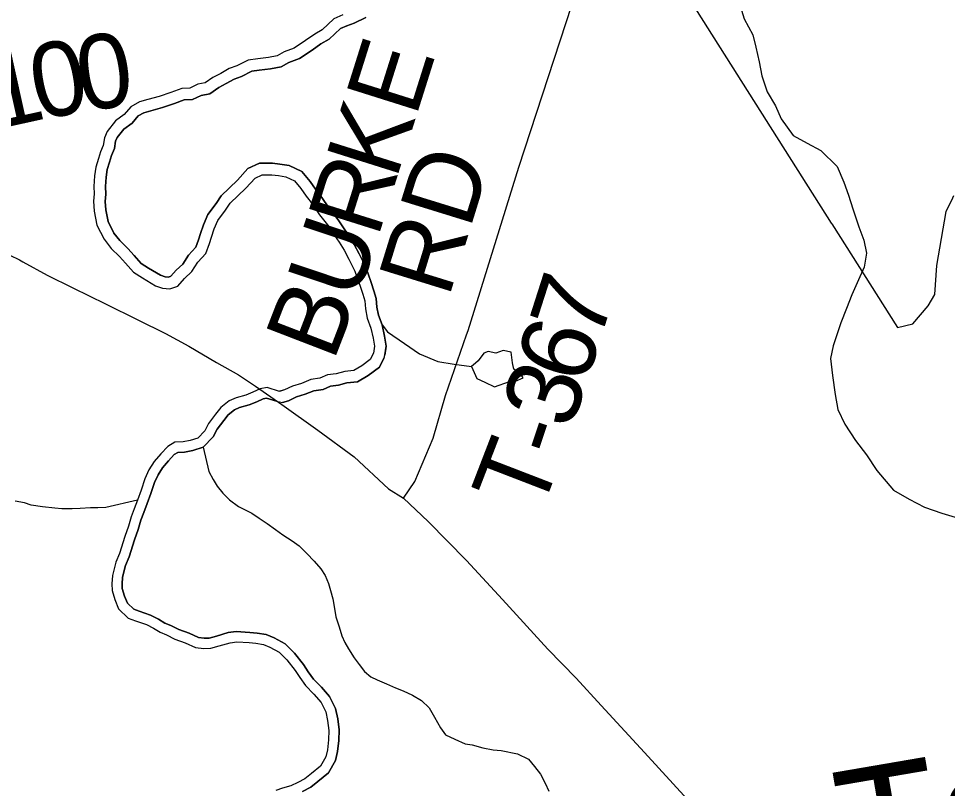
# Model space of a CAD drawing. Extents: x 1310247 to 1664935, y 235267 to 584339.
# Drawn here: x 1510976 to 1514722, y 357083 to 360189 of the extents above; entities that cross this region are included whole.
import ezdxf

# ---------------------------------------------------------------- set-up
doc = ezdxf.new("R2010")
doc.units = 0
for name, color, linetype in [('GM_X_Minor_Lake', 7, 'Continuous'), ('GM_X_Minor_River', 7, 'Continuous'), ('GM_X_Minor_River_Text', 7, 'Continuous'), ('GM_X_State_Route', 7, 'Continuous'), ('GM_X_Township_Road', 7, 'Continuous'), ('GM_X_Township_Road_Text', 7, 'Continuous'), ('GM_X_Township_ROW', 7, 'Continuous')]:
    doc.layers.add(name, color=color, linetype=linetype)

msp = doc.modelspace()

# ---------------------------------------------------------------- linework, layer by layer
at = {"layer": 'GM_X_Minor_Lake'}
for points in [[(1512802.7, 358784.8), (1512823.9, 358736.2), (1512855.8, 358721.6), (1512895.6, 358702.9), (1512956.1, 358724), (1512980.2, 358725.6), (1513010.5, 358739.1), (1512996.8, 358759.4), (1512973, 358773.9), (1512967.4, 358800.1), (1512962.1, 358842.3), (1512930.1, 358848.9), (1512899.9, 358839.4), (1512869.9, 358845.9)], [(1512869.9, 358845.9), (1512851.7, 358838.2), (1512829.1, 358808.4), (1512818.9, 358798.5), (1512802.7, 358784.8)]]:
    msp.add_lwpolyline(points, dxfattribs=at)
at = {"layer": 'GM_X_Minor_River'}
msp.add_line((1512015.5, 358644.9), (1512040.2, 358639.7), dxfattribs=at)
for points in [[(1513885.8, 360240.7), (1513901.4, 360188.1), (1513936.4, 360123.3), (1513949.6, 360072.9), (1513962.7, 360014.4), (1513973.8, 359958), (1513994.8, 359893.4), (1514027.9, 359836.6), (1514051.1, 359784), (1514100.1, 359716.9), (1514155.8, 359685.9), (1514211.5, 359656.8), (1514276.6, 359591.5), (1514303.6, 359528.8), (1514322.8, 359476.2), (1514340, 359421.7), (1514364.8, 359349), (1514384, 359294.5), (1514395.2, 359242.1), (1514386.2, 359186), (1514363.3, 359134.2), (1514336.2, 359074.4), (1514315.2, 359018.5), (1514292.2, 358960.6), (1514260.5, 358868.8), (1514249.6, 358816.8), (1514258.5, 358748.3), (1514269.3, 358671.9), (1514280.3, 358611.4), (1514307.4, 358552.7), (1514350.4, 358485.8), (1514395.6, 358428.8), (1514436.7, 358365.8), (1514503.6, 358286.4), (1514567.2, 358249.2), (1514628.8, 358218), (1514698.6, 358192.8), (1514766.5, 358173.6)], [(1512283.5, 360203.5), (1512247.2, 360188.3), (1512200.2, 360143.2), (1512169.9, 360125.8), (1512133.3, 360100.5), (1512086.7, 360069.5), (1512046.4, 360054.3), (1512018.1, 360038.9), (1511984, 360031.6), (1511940, 360026.6), (1511901.9, 360021.4), (1511855.4, 359998.4), (1511825.2, 359987), (1511790.8, 359967.7), (1511758.5, 359950.4), (1511728.1, 359929), (1511698, 359923.6), (1511665.7, 359908.3), (1511633.7, 359907), (1511589.4, 359889.9), (1511543.1, 359874.9), (1511496.9, 359861.9), (1511462.7, 359852.6), (1511428.3, 359833.3), (1511401.6, 359801.8), (1511367.1, 359776.5), (1511332.2, 359733.2), (1511321.6, 359707.3), (1511317, 359677.3), (1511306.4, 359651.5), (1511297.8, 359623.6), (1511287, 359589.8), (1511282.2, 359553.8), (1511279.3, 359511.7), (1511280.6, 359481.6), (1511277.9, 359451.5), (1511281, 359411.4), (1511291.8, 359355), (1511320.4, 359298.2), (1511349.6, 359261.4), (1511382.8, 359228.6), (1511406.2, 359202), (1511439.3, 359165.2), (1511474.7, 359142.3), (1511528, 359111), (1511555.7, 359100.4), (1511585.6, 359097.7), (1511617.8, 359109), (1511644.5, 359140.5), (1511675, 359168), (1511697.9, 359205.6), (1511730.6, 359240.9), (1511745.5, 359280.7), (1511754, 359306.6), (1511764.8, 359340.5), (1511779.5, 359374.2), (1511810.4, 359415.7), (1511829, 359443.3), (1511892.3, 359504.1), (1511929.2, 359545.4), (1511957.4, 359558.8), (1511997.4, 359558), (1512023.3, 359555.4), (1512053.1, 359550.7), (1512088.7, 359533.9), (1512114, 359503.2), (1512135.3, 359472.7), (1512160.5, 359440), (1512189.5, 359397.2), (1512226.4, 359350.3), (1512249.5, 359313.7), (1512268.9, 359287.2), (1512288.2, 359254.7), (1512307.3, 359218.1), (1512332.2, 359169.5), (1512341.6, 359143.2), (1512352.8, 359108.8), (1512364.1, 359076.5), (1512371.5, 359050.2), (1512374.7, 359018.1), (1512381.9, 358979.8), (1512396.9, 358939.3), (1512406, 358899), (1512411.3, 358866.8), (1512406.7, 358838.9)], [(1512451.7, 358824.5), (1512458.7, 358866.8), (1512451.9, 358908), (1512441.8, 358952.7), (1512427.1, 358992.3), (1512421, 359024.7), (1512417.6, 359059), (1512408.7, 359090.5), (1512397.1, 359123.8), (1512385.8, 359158.3), (1512375.2, 359188), (1512348.8, 359239.6), (1512329, 359277.5), (1512308, 359313), (1512288.2, 359340), (1512264.6, 359377.3), (1512227.3, 359424.9), (1512198.4, 359467.5), (1512173, 359500.4), (1512151.2, 359531.5), (1512118.1, 359571.7), (1512067, 359595.9), (1512029.2, 359601.8), (1512000.2, 359604.7), (1511947.4, 359605.8), (1511900.6, 359583.6), (1511858.6, 359536.6), (1511793, 359473.6), (1511772.3, 359442.7), (1511738.8, 359397.9), (1511721, 359356.9), (1511709.6, 359321), (1511701.4, 359296.3), (1511690, 359266), (1511660.3, 359233.9), (1511638.7, 359198.2), (1511610.9, 359173.2), (1511590.3, 359149), (1511579.6, 359145.2), (1511566.3, 359146.4), (1511548.3, 359153.3), (1511499.2, 359182.1), (1511469.9, 359201.1), (1511441.1, 359233.1), (1511416.8, 359260.7), (1511384.5, 359292.7), (1511360, 359323.5), (1511336.5, 359370.2), (1511327.5, 359417.5), (1511324.9, 359451.3), (1511327.5, 359480.5), (1511326.1, 359511.1), (1511328.8, 359549), (1511332.8, 359579.5), (1511342.4, 359609.6), (1511350.5, 359635.7), (1511362.3, 359664.7), (1511367, 359694.7), (1511372.9, 359709.1), (1511399.7, 359742.4), (1511433.7, 359767.4), (1511458.5, 359796.7), (1511480.5, 359809), (1511509.3, 359816.8), (1511556.6, 359830.1), (1511605, 359845.8), (1511643.3, 359860.6), (1511677.1, 359862), (1511712.3, 359878.7), (1511746.4, 359884.8), (1511783.1, 359910.5), (1511813.3, 359926.7), (1511845, 359944.5), (1511874.1, 359955.4), (1511915.8, 359976.1), (1511945.8, 359980.2), (1511991.5, 359985.4), (1512034.5, 359994.6), (1512065.9, 360011.7), (1512108.2, 360027.6), (1512159.6, 360061.8), (1512194.8, 360086.2), (1512228.4, 360105.4), (1512273.3, 360148.5), (1512299.9, 360159.7), (1512329.6, 360169.6), (1512375.6, 360192.6)], [(1512375.6, 360192.6), (1512329.6, 360169.6), (1512299.9, 360159.7), (1512273.3, 360148.5), (1512228.4, 360105.4), (1512194.8, 360086.2), (1512159.6, 360061.8), (1512108.2, 360027.6), (1512065.9, 360011.7), (1512034.5, 359994.6), (1511991.5, 359985.4), (1511945.8, 359980.2), (1511915.8, 359976.1), (1511874.1, 359955.4), (1511845, 359944.5), (1511813.3, 359926.7), (1511783.1, 359910.5), (1511746.4, 359884.8), (1511712.3, 359878.7), (1511677.1, 359862), (1511643.3, 359860.6), (1511605, 359845.8), (1511556.6, 359830.1), (1511509.3, 359816.8), (1511480.5, 359809), (1511458.5, 359796.7), (1511433.7, 359767.4), (1511399.7, 359742.4), (1511372.9, 359709.1), (1511367, 359694.7), (1511362.3, 359664.7), (1511350.5, 359635.7), (1511342.4, 359609.6), (1511332.8, 359579.5), (1511328.8, 359549), (1511326.1, 359511.1), (1511327.5, 359480.5), (1511324.9, 359451.3), (1511327.5, 359417.5), (1511336.5, 359370.2), (1511360, 359323.5), (1511384.5, 359292.7), (1511416.8, 359260.7), (1511441.1, 359233.1), (1511469.9, 359201.1), (1511499.2, 359182.1), (1511548.3, 359153.3), (1511566.3, 359146.4), (1511579.6, 359145.2), (1511590.3, 359149), (1511610.9, 359173.2), (1511638.7, 359198.2), (1511660.3, 359233.9), (1511690, 359266), (1511701.4, 359296.3), (1511709.6, 359321), (1511721, 359356.9), (1511738.8, 359397.9), (1511772.3, 359442.7), (1511793, 359473.6), (1511858.6, 359536.6), (1511900.6, 359583.6), (1511947.4, 359605.8), (1512000.2, 359604.7), (1512029.2, 359601.8), (1512067, 359595.9), (1512118.1, 359571.7), (1512151.2, 359531.5), (1512173, 359500.4), (1512198.4, 359467.5), (1512227.3, 359424.9), (1512264.6, 359377.3), (1512288.2, 359340), (1512308, 359313), (1512329, 359277.5), (1512348.8, 359239.6), (1512375.2, 359188), (1512385.8, 359158.3), (1512397.1, 359123.8), (1512408.7, 359090.5), (1512417.6, 359059), (1512421, 359024.7), (1512427.1, 358992.3), (1512441.8, 358952.7), (1512451.9, 358908), (1512458.7, 358866.8), (1512452.8, 358831.2)], [(1512441.8, 358952.7), (1512464, 358925), (1512531.4, 358877.6), (1512592.9, 358836.5), (1512666.6, 358805.1), (1512732.6, 358794), (1512802.7, 358784.8)], [(1512406.7, 358838.9), (1512394.1, 358813.1), (1512359.6, 358787.7), (1512327.2, 358768.4), (1512291.2, 358765.2), (1512257, 358755.9), (1512220.9, 358750.7), (1512190.7, 358737.3), (1512154.6, 358732.1), (1512116.3, 358716.9), (1512080.1, 358705.7), (1512047.8, 358690.3), (1512027.4, 358684.7)], [(1512406.7, 358838.9), (1512394.1, 358813.1), (1512359.6, 358787.7), (1512327.2, 358768.4), (1512291.2, 358765.2), (1512257, 358755.9), (1512220.9, 358750.7), (1512190.7, 358737.3), (1512154.6, 358732.1), (1512116.3, 358716.9), (1512080.1, 358705.7), (1512047.8, 358690.3), (1512027.7, 358684.8)], [(1512040.2, 358639.7), (1512064.2, 358646.4), (1512097.1, 358662), (1512131.9, 358672.8), (1512166.7, 358686.6), (1512203.7, 358692), (1512234, 358705.3), (1512266.5, 358710), (1512299.4, 358719), (1512342, 358722.8), (1512385.4, 358748.7), (1512431.1, 358782.2), (1512451.7, 358824.5)], [(1512448.7, 358818.4), (1512431.1, 358782.2), (1512385.4, 358748.7), (1512342, 358722.8), (1512299.4, 358719), (1512266.5, 358710), (1512234, 358705.3), (1512203.7, 358692), (1512166.7, 358686.6), (1512131.9, 358672.8), (1512097.1, 358662), (1512064.2, 358646.4), (1512040.2, 358639.7)], [(1512027.4, 358684.7), (1511978.1, 358699.7), (1511950.1, 358694.4), (1511919.9, 358681), (1511891.6, 358669.6), (1511853.4, 358658.4), (1511825.2, 358647), (1511790.7, 358619.7), (1511770.1, 358592.1), (1511741.4, 358554.6), (1511726.7, 358524.9), (1511698, 358495.4), (1511667.8, 358486), (1511639.7, 358480.6), (1511605.7, 358479.3), (1511577.4, 358462), (1511548.8, 358432.5), (1511522.2, 358401), (1511501.5, 358367.4), (1511484.7, 358331.7), (1511469.7, 358285.9), (1511454.8, 358246.1), (1511442, 358210.3), (1511429.3, 358178.5), (1511418.5, 358140.6), (1511403.6, 358098.8), (1511382.1, 358031.1), (1511367.3, 357995.3), (1511354.1, 357941.5), (1511351.4, 357907.5), (1511352.8, 357881.4), (1511363.9, 357845.1), (1511379, 357806.7), (1511418.1, 357769.8), (1511447.8, 357759.1), (1511491.4, 357744.1), (1511519.1, 357729.4), (1511546.6, 357712.8), (1511572.4, 357702.2), (1511605.9, 357685.4), (1511647.5, 357670.4), (1511689, 357651.5), (1511722.8, 357646.7), (1511750.8, 357648.1), (1511784.9, 357657.4), (1511829.2, 357670.4), (1511855.3, 357673.9), (1511905.1, 357670.8), (1511933, 357668.1), (1511962.9, 357663.5), (1511988.7, 357652.8), (1512026.2, 357632), (1512057.5, 357601.1), (1512090.5, 357558.3), (1512109.8, 357529.8), (1512133.1, 357497.2), (1512166.2, 357462.3), (1512195.5, 357429.6), (1512214.6, 357391), (1512221.8, 357356.7), (1512226.9, 357316.5), (1512226.1, 357278.4), (1512221.2, 357238.3), (1512214.5, 357210.4), (1512193.7, 357172.7), (1512157.1, 357143.4), (1512130.6, 357121.9), (1512102.3, 357106.5), (1512074, 357093), (1512039.8, 357083.8), (1512013.7, 357074.3)], [(1512027.7, 358684.6), (1511978.1, 358699.7), (1511950.1, 358694.4), (1511919.9, 358681), (1511891.6, 358669.6), (1511853.4, 358658.4), (1511825.2, 358647), (1511790.7, 358619.7), (1511770.1, 358592.1), (1511741.4, 358554.6), (1511726.7, 358524.9), (1511698, 358495.4), (1511667.8, 358486), (1511639.7, 358480.6), (1511605.7, 358479.3), (1511577.4, 358462), (1511548.8, 358432.5), (1511522.2, 358401), (1511501.5, 358367.4), (1511484.7, 358331.7), (1511469.7, 358285.9), (1511454.8, 358246.1), (1511442, 358210.3), (1511429.3, 358178.5), (1511418.5, 358140.6), (1511403.6, 358098.8), (1511382.1, 358031.1), (1511367.3, 357995.3), (1511354.1, 357941.5), (1511351.4, 357907.5), (1511352.8, 357881.4), (1511363.9, 357845.1), (1511379, 357806.7), (1511418.1, 357769.8), (1511447.8, 357759.1), (1511491.4, 357744.1), (1511519.1, 357729.4), (1511546.6, 357712.8), (1511572.4, 357702.2), (1511605.9, 357685.4), (1511647.5, 357670.4), (1511689, 357651.5), (1511722.8, 357646.7), (1511750.8, 357648.1), (1511784.9, 357657.4), (1511829.2, 357670.4), (1511855.3, 357673.9), (1511905.1, 357670.8), (1511933, 357668.1), (1511962.9, 357663.5), (1511988.7, 357652.8), (1512026.2, 357632), (1512057.5, 357601.1), (1512090.5, 357558.3), (1512109.8, 357529.8), (1512133.1, 357497.2), (1512166.2, 357462.3), (1512195.5, 357429.6), (1512214.6, 357391), (1512221.8, 357356.7), (1512226.9, 357316.5), (1512226.1, 357278.4), (1512221.2, 357238.3), (1512214.5, 357210.4), (1512193.7, 357172.7), (1512157.1, 357143.4), (1512130.6, 357121.9), (1512102.3, 357106.5), (1512074, 357093), (1512039.8, 357083.8), (1512013.7, 357074.3)], [(1512121.1, 357069.5), (1512153.8, 357087.3), (1512183.1, 357111.1), (1512226, 357145.4), (1512253.6, 357195.3), (1512262.1, 357231), (1512267.5, 357275.4), (1512268.5, 357318.6), (1512262.8, 357363.6), (1512254.1, 357404.7), (1512230.1, 357453), (1512196.7, 357490.5), (1512165.1, 357523.7), (1512143.9, 357553.5), (1512124.1, 357582.6), (1512088.6, 357628.7), (1512051.3, 357665.5), (1512006.8, 357690.3), (1511974.2, 357703.7), (1511938.2, 357709.3), (1511908.4, 357712.1), (1511853.8, 357715.5), (1511820.5, 357711.1), (1511773.6, 357697.3), (1511744.3, 357689.3), (1511724.7, 357688.4), (1511700.8, 357691.7), (1511663.2, 357708.9), (1511622.3, 357723.6), (1511589.6, 357740), (1511565.4, 357750), (1511539.5, 357765.6), (1511508, 357782.3), (1511461.6, 357798.2), (1511440.3, 357805.9), (1511414.3, 357830.5), (1511403.1, 357858.8), (1511393.9, 357888.7), (1511393, 357906.9), (1511395.2, 357934.8), (1511406.9, 357982.4), (1511421.1, 358016.9), (1511442.9, 358085.6), (1511458, 358127.9), (1511468.7, 358165.1), (1511480.9, 358195.6), (1511493.8, 358231.9), (1511508.9, 358272.2), (1511523.3, 358316.3), (1511538, 358347.6), (1511555.9, 358376.6), (1511579.6, 358404.6), (1511603.6, 358429.3), (1511618.2, 358438.3), (1511644.4, 358439.2), (1511677.9, 358445.7), (1511720.4, 358458.9), (1511761, 358500.6), (1511776.8, 358532.6), (1511803.2, 358567), (1511820.7, 358590.5), (1511846.3, 358610.7), (1511867.1, 358619.1), (1511905.3, 358630.3), (1511936, 358642.8), (1511962.5, 358654.5), (1511975.8, 358657), (1512015.5, 358644.9)], [(1512015.5, 358644.9), (1511975.8, 358657), (1511962.5, 358654.5), (1511936, 358642.8), (1511905.3, 358630.3), (1511867.1, 358619.1), (1511846.3, 358610.7), (1511820.7, 358590.5), (1511803.2, 358567), (1511776.8, 358532.6), (1511761, 358500.6), (1511720.4, 358458.9), (1511677.9, 358445.7), (1511644.4, 358439.2), (1511618.2, 358438.3), (1511603.6, 358429.3), (1511579.6, 358404.6), (1511555.9, 358376.6), (1511538, 358347.6), (1511523.3, 358316.3), (1511508.9, 358272.2), (1511493.8, 358231.9), (1511480.9, 358195.6), (1511468.7, 358165.1), (1511458, 358127.9), (1511442.9, 358085.6), (1511421.1, 358016.9), (1511406.9, 357982.4), (1511395.2, 357934.8), (1511393, 357906.9), (1511393.9, 357888.7), (1511403.1, 357858.8), (1511414.3, 357830.5), (1511440.3, 357805.9), (1511461.6, 357798.2), (1511508, 357782.3), (1511539.5, 357765.6), (1511565.4, 357750), (1511589.6, 357740), (1511622.3, 357723.6), (1511663.2, 357708.9), (1511700.8, 357691.7), (1511724.7, 357688.4), (1511744.3, 357689.3), (1511773.6, 357697.3), (1511820.5, 357711.1), (1511853.8, 357715.5), (1511908.4, 357712.1), (1511938.2, 357709.3), (1511974.2, 357703.7), (1512006.8, 357690.3), (1512051.3, 357665.5), (1512088.6, 357628.7), (1512124.1, 357582.6), (1512143.9, 357553.5), (1512165.1, 357523.7), (1512196.7, 357490.5), (1512230.1, 357453), (1512254.1, 357404.7), (1512262.8, 357363.6), (1512268.5, 357318.6), (1512267.5, 357275.4), (1512262.1, 357231), (1512253.6, 357195.3), (1512226, 357145.4), (1512183.1, 357111.1), (1512153.8, 357087.3), (1512121.1, 357069.5)], [(1511720.4, 358458.9), (1511743.1, 358361.3), (1511760.4, 358328.8), (1511775.9, 358302.4), (1511799.3, 358273.8), (1511826.8, 358247.2), (1511862.2, 358220.4), (1511915.7, 358193.2), (1511945.3, 358172.5), (1511978.8, 358151.7), (1512012.3, 358127), (1512041.9, 358106.3), (1512079.4, 358081.5), (1512107, 358060.8), (1512138.4, 358030.1), (1512167.8, 357999.4), (1512195.1, 357968.7), (1512212.6, 357942.3), (1512225.9, 357909.9), (1512233.3, 357881.7), (1512242.6, 357847.4), (1512248, 357817.2), (1512255.1, 357774.9), (1512268.2, 357734.5), (1512279.5, 357698.2), (1512290.9, 357671.9), (1512306.4, 357645.5), (1512329.6, 357608.9), (1512349.1, 357582.4), (1512370.5, 357553.9), (1512396.1, 357533.3), (1512421.8, 357520.7), (1512459.5, 357503.9), (1512495.2, 357489.1), (1512527, 357476.4), (1512564.6, 357459.5), (1512600.2, 357436.7), (1512631.6, 357408), (1512652.8, 357369.5), (1512677.9, 357326.8), (1512697.3, 357298.3), (1512735, 357281.5), (1512776.6, 357262.6), (1512804.5, 357258), (1512848.3, 357247), (1512890.2, 357238.1), (1512922.2, 357235.5), (1512987.9, 357222.1), (1513031.5, 357201.1), (1513056.9, 357170.5), (1513080.2, 357139.9), (1513099.5, 357103.4), (1513114.8, 357071)], [(1511454.8, 358246.1), (1511327.8, 358215.5), (1511295.7, 358214.1), (1511265.7, 358214.8), (1511223.6, 358211.6), (1511191.6, 358210.3), (1511149.5, 358211.2), (1511121.6, 358213.8), (1511071.7, 358218.8), (1511025.8, 358225.8), (1510999.9, 358234.4), (1510962.1, 358241.2)]]:
    msp.add_lwpolyline(points, dxfattribs=at)
at = {"layer": 'GM_X_State_Route'}
for points in [[(1508840, 360904.1), (1508940.4, 360768.2), (1509093.4, 360580.7), (1509200.5, 360460.2), (1509297.1, 360355.9), (1509418.6, 360248.8), (1509525.8, 360146.4), (1509676, 360029.7), (1509841.4, 359902.5), (1510039.4, 359758), (1510167.6, 359662.4), (1510390.5, 359520.8), (1510557.5, 359418.4), (1510751.4, 359317.1), (1510900.3, 359253), (1510979.7, 359214.7), (1510992.4, 359207.8)], [(1510992.4, 359207.8), (1511090.8, 359153.6), (1511195, 359101.8), (1511326, 359037.8), (1511456.1, 358973.7), (1511568, 358918.2), (1511662.7, 358866.5), (1511773.7, 358801.5), (1511862.6, 358750.8), (1511931.5, 358705.8), (1512037.7, 358631.2), (1512183.1, 358527.9), (1512328.7, 358421.1), (1512467.7, 358291), (1512527.5, 358253.4), (1512627.9, 358159.7), (1512781.9, 358002.8), (1512927.3, 357844.9), (1513110, 357645), (1513224.3, 357526.9), (1513324.7, 357417.4), (1513500.3, 357227.5), (1513672.9, 357038.1)]]:
    msp.add_lwpolyline(points, dxfattribs=at)
at = {"layer": 'GM_X_Township_Road'}
for points in [[(1512782.3, 358912.3), (1512788.6, 358930.6), (1512993.5, 359589.6)], [(1514255.5, 359360.4), (1514520.1, 358942.1), (1514582.4, 358957), (1514643.9, 359030), (1514670.8, 359075.7), (1514679, 359191.9), (1514717, 359409.8), (1514743.3, 359465.9), (1514747.5, 359474.8)], [(1512527.5, 358253.4), (1512573.4, 358320.3), (1512648, 358495.4), (1512698, 358667.7), (1512782.3, 358912.3)]]:
    msp.add_lwpolyline(points, dxfattribs=at)
at = {"layer": 'GM_X_Township_ROW'}
for points in [[(1512993.5, 359589.6), (1513374, 360753.9)], [(1513374, 360753.9), (1514253.4, 359363.7), (1514255.5, 359360.4)]]:
    msp.add_lwpolyline(points, dxfattribs=at)

# ---------------------------------------------------------------- texts
at = {"layer": 'GM_X_Minor_River_Text'}
msp.add_text('Town', height=500, rotation=9.7323, dxfattribs=at).set_placement((1514328.4, 356650.4))
at = {"layer": 'GM_X_Township_Road_Text'}
for s, rotation, p in [('0', 8.3792, (1511231.7, 359812.2)), ('0', 10.7124, (1511053.3, 359778.4)), ('E', 72.5009, (1512577.3, 359786.2)), ('1', 12.4546, (1510875.2, 359739)), ('K', 72.5028, (1512497.9, 359534.4)), ('RD', 72.8237, (1512709.7, 359056.9)), ('R', 72.5105, (1512423.9, 359299.4)), ('U', 71.4731, (1512338.2, 359043.6)), ('7', 72.2422, (1513317.9, 358879.3)), ('B', 68.9154, (1512244.7, 358800.1)), ('6', 72.4349, (1513262.2, 358703.4)), ('3', 71.7639, (1513203.2, 358524.2)), ('-', 71.6754, (1513164.3, 358406.8)), ('T', 68.9045, (1513078.2, 358182.5))]:
    msp.add_text(s, height=300, rotation=rotation, dxfattribs=at).set_placement(p)

doc.saveas('drawing.dxf')
